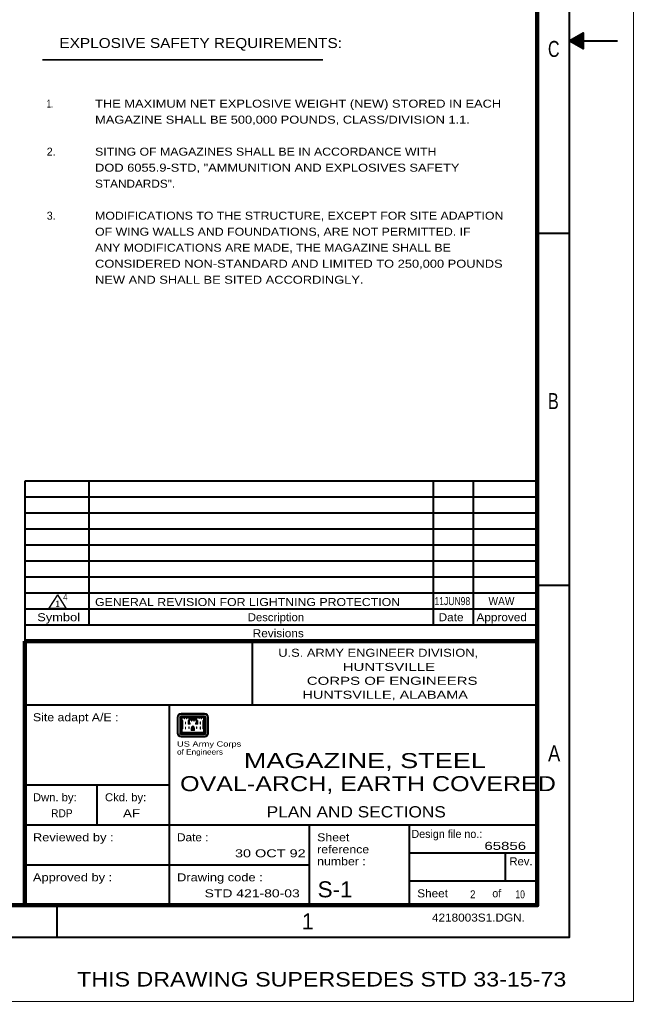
# Model space of a CAD drawing. Extents: x -24.3 to 17.7, y -17.6 to 12.4.
# Drawn here: x 8.07 to 17.66, y -17.61 to -2.28 of the extents above; entities that cross this region are included whole.
import ezdxf
from ezdxf.enums import TextEntityAlignment as Align

# ---------------------------------------------------------------- set-up
doc = ezdxf.new("R2010")
doc.units = 0
doc.header["$LTSCALE"] = 0.05
doc.layers.add('1', color=7, linetype='Continuous', lineweight=13)
doc.layers.add('2', color=7, linetype='Continuous', lineweight=13)

msp = doc.modelspace()

# ---------------------------------------------------------------- linework, layer by layer
at = {"layer": '1', "lineweight": 40}
for p, q in [((16.65731, -2.6106), (17.40731, -2.6106)), ((16.15731, -5.6106), (16.65731, -5.6106)), ((8.15731, -9.4856), (8.15731, -11.9856)), ((16.15731, -9.4856), (8.15731, -9.4856)), ((9.15731, -9.4856), (9.15731, -11.7356)), ((14.53231, -9.4856), (14.53231, -11.7356)), ((15.15731, -9.4856), (15.15731, -11.7356)), ((16.15731, -9.7356), (8.15731, -9.7356)), ((16.15731, -9.9856), (8.15731, -9.9856)), ((16.15731, -10.2356), (8.15731, -10.2356)), ((16.15731, -10.4856), (8.15731, -10.4856)), ((16.15731, -10.7356), (8.15731, -10.7356)), ((16.15731, -10.9856), (8.15731, -10.9856)), ((16.15731, -11.1106), (16.65731, -11.1106)), ((16.15731, -11.2356), (8.15731, -11.2356)), ((16.15731, -11.4856), (8.15731, -11.4856)), ((16.15731, -11.7356), (8.15731, -11.7356)), ((11.70531, -11.9856), (11.70531, -12.9856)), ((16.15731, -12.9856), (8.15731, -12.9856)), ((10.40731, -12.9856), (10.40731, -16.1106)), ((10.40731, -14.2356), (8.15731, -14.2356)), ((9.28231, -14.2356), (9.28231, -14.8606)), ((16.15731, -14.8606), (8.15731, -14.8606)), ((12.59531, -14.8606), (12.59531, -16.1106)), ((14.15731, -14.8606), (14.15731, -16.1106)), ((16.15731, -15.2986), (14.15731, -15.2986)), ((15.65731, -15.2986), (15.65731, -15.7356)), ((12.59531, -15.4856), (8.15731, -15.4856)), ((16.15731, -15.7356), (14.15731, -15.7356)), ((8.65731, -16.1106), (8.65731, -16.6106))]:
    msp.add_line(p, q, dxfattribs=at)
at = {"layer": '1', "lineweight": 35}
msp.add_line((8.43031, -2.90357), (12.80731, -2.90357), dxfattribs=at)
at = {"layer": '1', "lineweight": 25}
for p, q in [((8.53532, -11.46962), (8.66832, -11.26062)), ((8.80132, -11.46962), (8.66832, -11.26062)), ((8.53532, -11.46962), (8.80132, -11.46962))]:
    msp.add_line(p, q, dxfattribs=at)
at = {"layer": '1', "lineweight": 90}
for p, q in [((8.15731, -11.9856), (8.15731, -16.1106)), ((16.15731, -11.9856), (8.15731, -11.9856))]:
    msp.add_line(p, q, dxfattribs=at)
at = {"layer": '1'}
for p, q in [((10.53231, -13.1756), (10.53231, -13.4216)), ((10.53631, -13.1756), (10.53631, -13.4216)), ((10.54231, -13.1756), (10.54231, -13.4216)), ((10.54731, -13.1756), (10.54731, -13.4216)), ((10.55231, -13.1756), (10.55231, -13.4216)), ((10.57331, -13.1756), (10.57331, -13.4216)), ((10.57831, -13.1756), (10.57831, -13.4216)), ((10.58331, -13.1756), (10.58331, -13.4216)), ((10.58831, -13.1756), (10.58831, -13.4216)), ((10.59331, -13.1756), (10.59331, -13.4216)), ((10.96131, -13.1106), (10.59731, -13.1106)), ((10.96131, -13.1146), (10.59731, -13.1146)), ((10.96131, -13.1196), (10.59731, -13.1196)), ((10.96131, -13.1246), (10.59731, -13.1246)), ((10.96131, -13.1306), (10.59731, -13.1306)), ((10.96131, -13.1506), (10.59731, -13.1506)), ((10.96131, -13.1566), (10.59731, -13.1566)), ((10.96131, -13.1616), (10.59731, -13.1616)), ((10.96131, -13.1666), (10.59731, -13.1666)), ((10.96131, -13.1716), (10.59731, -13.1716)), ((10.59931, -13.1756), (10.59931, -13.4196)), ((10.60431, -13.1756), (10.60431, -13.4146)), ((10.72331, -13.1766), (10.83531, -13.1766)), ((10.72331, -13.1816), (10.83531, -13.1816)), ((10.95431, -13.1756), (10.95431, -13.4146)), ((10.95931, -13.1756), (10.95931, -13.4196)), ((10.96431, -13.1756), (10.96431, -13.4216)), ((10.97031, -13.1756), (10.97031, -13.4216)), ((10.97531, -13.1756), (10.97531, -13.4216)), ((10.98031, -13.1756), (10.98031, -13.4216)), ((10.98531, -13.1756), (10.98531, -13.4216)), ((11.00631, -13.1756), (11.00631, -13.4216)), ((11.01131, -13.1756), (11.01131, -13.4216)), ((11.01731, -13.1756), (11.01731, -13.4216)), ((11.02231, -13.1756), (11.02231, -13.4216)), ((11.02531, -13.1756), (11.02531, -13.4216)), ((10.60831, -13.2276), (10.60831, -13.3536)), ((10.61331, -13.2326), (10.61331, -13.3476)), ((10.72331, -13.1866), (10.83531, -13.1866)), ((10.72331, -13.1926), (10.83531, -13.1926)), ((10.72331, -13.1976), (10.83531, -13.1976)), ((10.72331, -13.2026), (10.83531, -13.2026)), ((10.72331, -13.2076), (10.83531, -13.2076)), ((10.75531, -13.3786), (10.75531, -13.3386)), ((10.76031, -13.3786), (10.76031, -13.3386)), ((10.76531, -13.3786), (10.76531, -13.3386)), ((10.77031, -13.3786), (10.77031, -13.3386)), ((10.77631, -13.3786), (10.77631, -13.3386)), ((10.78231, -13.3786), (10.78231, -13.3386)), ((10.78731, -13.3786), (10.78731, -13.3386)), ((10.79331, -13.3786), (10.79331, -13.3386)), ((10.79831, -13.3786), (10.79831, -13.3386)), ((10.80331, -13.3786), (10.80331, -13.3386)), ((10.94531, -13.2326), (10.94531, -13.3476)), ((10.95031, -13.2276), (10.95031, -13.3526)), ((10.96131, -13.4246), (10.59731, -13.4246)), ((10.96131, -13.4296), (10.59731, -13.4296)), ((10.96131, -13.4356), (10.59731, -13.4356)), ((10.96131, -13.4406), (10.59731, -13.4406)), ((10.96131, -13.4456), (10.59731, -13.4456)), ((10.96131, -13.4666), (10.59731, -13.4666)), ((10.96131, -13.4716), (10.59731, -13.4716)), ((10.96131, -13.4766), (10.59731, -13.4766)), ((10.96131, -13.4826), (10.59731, -13.4826)), ((10.96131, -13.4856), (10.59731, -13.4856)), ((10.95931, -13.4196), (10.59931, -13.4196)), ((10.95431, -13.4146), (10.60431, -13.4146)), ((10.75531, -13.3786), (10.80331, -13.3786)), ((17.65731, -17.6106), (-24.34269, -17.6106))]:
    msp.add_line(p, q, dxfattribs=at)
for points in [[(-24.34269, 12.3894), (17.65731, 12.3894), (17.65731, -17.6106)], [(10.71731, -13.2326), (10.71431, -13.2356), (10.71431, -13.2696), (10.72531, -13.2696), (10.71831, -13.2616), (10.71831, -13.2316)], [(10.84131, -13.2326), (10.84431, -13.2356), (10.84431, -13.2696), (10.83331, -13.2696), (10.84031, -13.2616), (10.84031, -13.2316)]]:
    msp.add_lwpolyline(points, dxfattribs=at)
at = {"layer": '1', "lineweight": 40}
for points in [[(-23.34269, -16.6106), (-23.34269, 11.3894), (16.65731, 11.3894), (16.65731, -16.6106)], [(16.65731, -2.6106), (16.87431, -2.4856), (16.87431, -2.7356)]]:
    msp.add_lwpolyline(points, close=True, dxfattribs=at)
at = {"layer": '1', "lineweight": 90}
msp.add_lwpolyline([(-21.84269, 10.8894), (16.15731, 10.8894), (16.15731, -16.1106), (-21.84269, -16.1106)], close=True, dxfattribs=at)
at = {"layer": '1', "lineweight": 40}
for points in [[(16.70031, -2.6106), (16.85331, -2.5216), (16.85331, -2.6996), (16.70131, -2.6116)], [(16.74031, -2.6116), (16.83231, -2.5576), (16.83231, -2.6636), (16.73931, -2.6096)], [(16.78231, -2.6116), (16.81231, -2.5936), (16.81231, -2.6276), (16.78531, -2.6126)]]:
    msp.add_lwpolyline(points, dxfattribs=at)
at = {"layer": '1'}
for points in [[(10.60831, -13.1756), (10.60831, -13.2226), (10.61831, -13.2326), (10.61831, -13.3476), (10.60831, -13.3586), (10.60831, -13.4106), (10.95031, -13.4106), (10.95031, -13.3586), (10.93931, -13.3476), (10.93931, -13.2326), (10.95031, -13.2226), (10.95031, -13.1756), (10.90531, -13.1756), (10.87031, -13.1756), (10.83831, -13.1756), (10.83831, -13.2226), (10.84931, -13.2326), (10.84931, -13.2746), (10.82431, -13.2746), (10.82431, -13.2706), (10.83531, -13.2596), (10.83531, -13.2126), (10.79031, -13.2126), (10.75531, -13.2126), (10.72331, -13.2126), (10.72331, -13.2596), (10.73431, -13.2706), (10.73431, -13.2746), (10.70931, -13.2746), (10.70931, -13.2326), (10.72031, -13.2226), (10.72031, -13.1756), (10.67431, -13.1756), (10.64031, -13.1756)], [(10.61331, -13.1806), (10.61331, -13.2206), (10.62431, -13.2306), (10.62431, -13.3496), (10.61331, -13.3606), (10.61331, -13.4056), (10.94531, -13.4056), (10.94531, -13.3606), (10.93431, -13.3496), (10.93431, -13.2306), (10.94531, -13.2206), (10.94531, -13.1806), (10.91331, -13.1806), (10.91331, -13.1996), (10.91031, -13.1996), (10.91031, -13.1806), (10.87831, -13.1806), (10.87831, -13.1996), (10.87531, -13.1996), (10.87531, -13.1806), (10.84331, -13.1806), (10.84331, -13.2206), (10.85431, -13.2306), (10.85431, -13.2796), (10.81931, -13.2796), (10.81931, -13.2686), (10.83031, -13.2576), (10.83031, -13.2176), (10.79831, -13.2176), (10.79831, -13.2366), (10.79531, -13.2366), (10.79531, -13.2176), (10.76331, -13.2176), (10.76331, -13.2366), (10.76031, -13.2366), (10.76031, -13.2176), (10.72831, -13.2176), (10.72831, -13.2576), (10.73931, -13.2686), (10.73931, -13.2796), (10.70431, -13.2796), (10.70431, -13.2306), (10.71531, -13.2206), (10.71531, -13.1806), (10.68331, -13.1806), (10.68331, -13.1996), (10.68031, -13.1996), (10.68031, -13.1806), (10.64831, -13.1806), (10.64831, -13.1996), (10.64531, -13.1996), (10.64531, -13.1806)], [(10.66231, -13.2446), (10.66231, -13.2796), (10.66531, -13.2796), (10.66531, -13.2446)], [(10.66231, -13.3246), (10.66231, -13.3596), (10.66531, -13.3596), (10.66531, -13.3246)], [(10.71731, -13.3246), (10.71731, -13.3496), (10.72031, -13.3496), (10.72031, -13.3246)], [(10.84131, -13.3246), (10.84131, -13.3496), (10.83831, -13.3496), (10.83831, -13.3246)], [(10.89631, -13.2446), (10.89631, -13.2796), (10.89231, -13.2796), (10.89231, -13.2446)], [(10.89631, -13.3246), (10.89631, -13.3596), (10.89231, -13.3596), (10.89231, -13.3246)]]:
    msp.add_lwpolyline(points, close=True, dxfattribs=at)
for centre, radius, start, end in [((10.59708, -13.17514), 0.06429, 89.99998, 179.99997), ((10.59708, -13.17514), 0.06057, 89.99998, 179.99997), ((10.59708, -13.17514), 0.05536, 89.99998, 179.99997), ((10.59708, -13.17514), 0.05015, 89.99998, 179.99997), ((10.59708, -13.17514), 0.04494, 89.99998, 179.99997), ((10.59708, -13.17514), 0.02411, 89.99998, 179.99997), ((10.59708, -13.17514), 0.0189, 89.99998, 179.99997), ((10.59708, -13.17514), 0.01369, 89.99998, 179.99997), ((10.59708, -13.17514), 0.00848, 89.99998, 179.99997), ((10.59708, -13.17514), 0.00327, 89.99998, 179.99997), ((10.96137, -13.17514), 0.06429, 359.99998, 89.99998), ((10.96137, -13.17514), 0.06057, 0.00002, 90.00002), ((10.96137, -13.17514), 0.05536, 0.00003, 90.00002), ((10.96137, -13.17514), 0.05015, 0.00002, 90.00002), ((10.96137, -13.17514), 0.04494, 0.00002, 90.00002), ((10.96137, -13.17514), 0.02411, 359.99998, 89.99998), ((10.96137, -13.17514), 0.0189, 359.99998, 89.99998), ((10.96137, -13.17514), 0.01369, 359.99998, 89.99998), ((10.96137, -13.17514), 0.00848, 359.99998, 89.99998), ((10.96137, -13.17514), 0.00327, 359.99998, 89.99998), ((10.7882, -13.34118), 0.03332, 105.66805, 176.05748), ((10.7882, -13.34118), 0.02811, 103.46979, 176.05748), ((10.7882, -13.34118), 0.0229, 103.46979, 176.05748), ((10.7882, -13.34118), 0.0177, 103.46979, 176.05748), ((10.77025, -13.34118), 0.01249, 3.94252, 76.53021), ((10.77025, -13.34118), 0.0177, 3.94252, 76.53021), ((10.77025, -13.34118), 0.0229, 3.94252, 76.53021), ((10.7882, -13.34118), 0.01249, 103.46979, 176.05748), ((10.77025, -13.34118), 0.02811, 3.94252, 76.53021), ((10.77025, -13.34118), 0.03332, 3.94252, 74.39486), ((10.59708, -13.42157), 0.06429, 180.00003, 270.00003), ((10.59708, -13.42157), 0.06057, 179.99998, 269.99997), ((10.59708, -13.42157), 0.05536, 179.99998, 269.99997), ((10.59708, -13.42157), 0.05015, 179.99998, 269.99997), ((10.59708, -13.42157), 0.04494, 179.99998, 269.99997), ((10.59708, -13.42157), 0.02411, 180.00003, 270.00003), ((10.59708, -13.42157), 0.0189, 180.00003, 270.00003), ((10.59708, -13.42157), 0.01369, 180.00003, 270.00003), ((10.59708, -13.42157), 0.00848, 180.00003, 270.00003), ((10.59708, -13.42157), 0.00327, 180.00003, 270.00003), ((10.96137, -13.42157), 0.06429, 270.00003, 0.00003), ((10.96137, -13.42157), 0.02411, 270.00003, 0.00003), ((10.96137, -13.42157), 0.0189, 270.00003, 0.00003), ((10.96137, -13.42157), 0.01369, 270.00003, 0.00003), ((10.96137, -13.42157), 0.00848, 270.00003, 0.00003), ((10.96137, -13.42157), 0.00327, 270.00003, 0.00003), ((10.96137, -13.42157), 0.04494, 270.00002, 0.00002), ((10.96137, -13.42157), 0.05015, 270.00002, 0.00002), ((10.96137, -13.42157), 0.05536, 270.00002, 0.00002), ((10.96137, -13.42157), 0.06057, 270.00002, 0.00002)]:
    msp.add_arc(centre, radius, start, end, dxfattribs=at)

# ---------------------------------------------------------------- texts
for s, height, width, p in [('EXPLOSIVE SAFETY REQUIREMENTS:', 0.156, 1.15, (8.69531, -2.72157)), ('THE MAXIMUM NET EXPLOSIVE WEIGHT (NEW) STORED IN EACH', 0.125, 1.2, (9.25231, -3.65257)), ('1.', 0.125, 0.65, (8.49731, -3.65257)), ('MAGAZINE SHALL BE 500,000 POUNDS, CLASS/DIVISION 1.1.', 0.125, 1.2, (9.25231, -3.90257)), ('SITING OF MAGAZINES SHALL BE IN ACCORDANCE WITH', 0.125, 1.15, (9.25231, -4.40257)), ('DOD 6055.9-STD, "AMMUNITION AND EXPLOSIVES SAFETY', 0.125, 1.2, (9.25231, -4.65257)), ('STANDARDS".', 0.125, 1.1, (9.25231, -4.90257)), ('MODIFICATIONS TO THE STRUCTURE, EXCEPT FOR SITE ADAPTION', 0.125, 1.15, (9.25231, -5.40257)), ('OF WING WALLS AND FOUNDATIONS, ARE NOT PERMITTED. IF', 0.125, 1.15, (9.25231, -5.65257)), ('ANY MODIFICATIONS ARE MADE, THE MAGAZINE SHALL BE', 0.125, 1.15, (9.25231, -5.90257)), ('CONSIDERED NON-STANDARD AND LIMITED TO 250,000 POUNDS', 0.125, 1.2, (9.25231, -6.15257)), ('NEW AND SHALL BE SITED ACCORDINGLY.', 0.125, 1.2, (9.25231, -6.40257)), ('Site adapt A/E :', 0.125, 1.15, (8.28231, -13.2356)), ('US Army Corps', 0.083, 1.3, (10.53231, -13.6316)), ('of Engineers', 0.083, 1.15, (10.53231, -13.7566)), ('Dwn. by:', 0.125, 1.05, (8.28231, -14.4856)), ('Ckd. by:', 0.125, 1.05, (9.40731, -14.4856)), ('Reviewed by :', 0.125, 1.2, (8.28231, -15.1106)), ('Date :', 0.125, 1.1, (10.53231, -15.1106)), ('Sheet', 0.125, 1.15, (12.72031, -15.1106)), ('reference', 0.125, 1.15, (12.72031, -15.2986)), ('number :', 0.125, 1.15, (12.72031, -15.4856)), ('Rev.', 0.125, 1.05, (15.72231, -15.4856)), ('Approved by :', 0.125, 1.2, (8.28231, -15.7356)), ('Drawing code :', 0.125, 1.2, (10.53231, -15.7356)), ('Sheet     ', 0.125, 1.1, (14.28231, -15.9856)), ('4218003S1.DGN.', 0.125, 1.1, (14.51231, -16.36469))]:
    msp.add_text(s, height=height, dxfattribs=dict(at, width=width)).set_placement(p)
for s, height, width, p in [('C', 0.25, 0.75, (16.41431, -2.8606)), ('B', 0.25, 0.75, (16.40831, -8.3606)), ('4', 0.1, 0.9, (8.78766, -11.34762)), ('GENERAL REVISION FOR LIGHTNING PROTECTION', 0.125, 1.15, (11.63367, -11.43647)), ('11JUN98', 0.125, 0.8, (14.83085, -11.42158)), ('WAW', 0.125, 0.95, (15.59757, -11.4216)), ('1', 0.1, 0.9, (8.66866, -11.45063)), ('Symbol', 0.125, 1.2, (8.68381, -11.6736)), ('Description', 0.125, 1.05, (12.07681, -11.6736)), ('Date', 0.125, 1.1, (14.81131, -11.6736)), ('Approved', 0.125, 1.1, (15.60181, -11.6736)), ('Revisions', 0.125, 1.1, (12.11281, -11.9236)), ('   U.S. ARMY ENGINEER DIVISION,   ', 0.125, 1.2, (13.67381, -12.2286)), ('           HUNTSVILLE             ', 0.125, 1.4, (13.90531, -12.4496)), ('       CORPS OF ENGINEERS         ', 0.125, 1.4, (13.95631, -12.6666)), ('      HUNTSVILLE, ALABAMA         ', 0.125, 1.35, (13.87631, -12.8846)), ('A', 0.25, 0.85, (16.42081, -13.8606)), ('PLAN AND SECTIONS', 0.175, 1.15, (13.33081, -14.7376)), ('2', 0.125, 0.9, (15.14981, -16.0016)), ('10', 0.125, 0.8, (15.88981, -16.0016)), ('THIS DRAWING SUPERSEDES STD 33-15-73', 0.226, 1.2, (12.79131, -17.3786))]:
    msp.add_text(s, height=height, dxfattribs=dict(at, width=width)).set_placement(p, align=Align.CENTER)
for s, p in [('2.', (8.49731, -4.40257)), ('3.', (8.49731, -5.40257)), ('Design file no.:', (14.19231, -15.0576))]:
    msp.add_text(s, height=0.125, dxfattribs=at).set_placement(p)
msp.add_text('of', height=0.125, dxfattribs=at).set_placement((15.59431, -15.9856), align=Align.RIGHT)
msp.add_text('1', height=0.2503, dxfattribs=at).set_placement((12.57431, -16.4856), align=Align.CENTER)
at = {"layer": '2'}
for s, height, width, p in [('       MAGAZINE, STEEL       ', 0.234, 1.35, (13.46481, -13.9676)), ('  OVAL-ARCH, EARTH COVERED   ', 0.234, 1.25, (13.56781, -14.3276)), ('RDP', 0.125, 0.95, (8.73381, -14.7356)), ('AF ', 0.125, 1.25, (9.85131, -14.7356))]:
    msp.add_text(s, height=height, dxfattribs=dict(at, width=width)).set_placement(p, align=Align.CENTER)
for s, width, p in [('         65856', 1.4, (15.98231, -15.2446)), ('30 OCT 92', 1.35, (12.54031, -15.3606)), ('STD 421-80-03', 1.3, (12.44831, -15.9856))]:
    msp.add_text(s, height=0.125, dxfattribs=dict(at, width=width)).set_placement(p, align=Align.RIGHT)
at = {"layer": '2', "width": 1.05}
msp.add_text(' S-1  ', height=0.25, dxfattribs=at).set_placement((12.62931, -15.9856))

doc.saveas('drawing.dxf')
